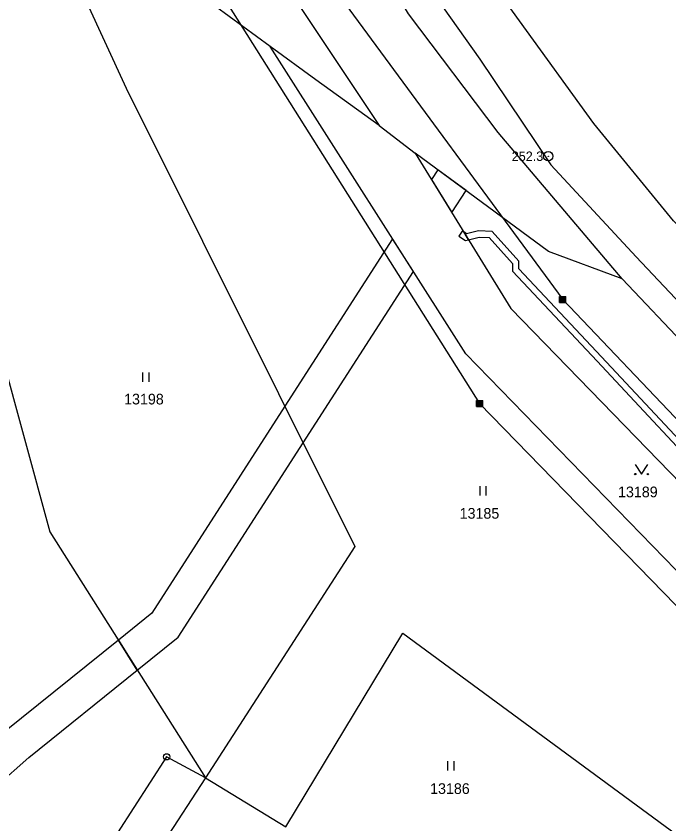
# Model space of a CAD drawing. Extents: x -821458 to -820266, y -1071458 to -1069826.
# Drawn here: x -820602.1 to -820498, y -1071105.6 to -1070976.8 of the extents above; entities that cross this region are included whole.
import ezdxf

# ---------------------------------------------------------------- set-up
doc = ezdxf.new("R2010")
doc.units = 0
for name, color, linetype in [('Vrstva 1', 7, 'Continuous'), ('Vrstva 13', 7, 'Continuous'), ('Vrstva 2', 7, 'Continuous'), ('Vrstva 3', 7, 'Continuous'), ('Vrstva 6', 7, 'Continuous'), ('Vrstva 8', 7, 'Continuous')]:
    doc.layers.add(name, color=color, linetype=linetype)

msp = doc.modelspace()

# ---------------------------------------------------------------- linework, layer by layer
at = {"layer": 'Vrstva 1'}
for p, q in [((-820561.6, -1070981.6), (-820570.28, -1070975.21)), ((-820544.2, -1070994.2), (-820538.47, -1070998.6)), ((-820517.2, -1071014.29), (-820538.47, -1070998.6)), ((-820505.46, -1071018.65), (-820517.2, -1071014.29)), ((-820488.98, -1071036.1), (-820505.46, -1071018.65)), ((-820571.9, -1071098.21), (-820578.53, -1071108.44)), ((-820571.9, -1071098.21), (-820559.1, -1071106.03))]:
    msp.add_line(p, q, dxfattribs=at)
for points in [[(-820505.46, -1071018.65), (-820525.24, -1070995.31), (-820539.52, -1070976.39), (-820562.83, -1070937.87), (-820572.14, -1070918.15), (-820580.6, -1070898.43)], [(-820575.41, -1070898.25), (-820570.53, -1070910.66), (-820562.59, -1070929.03), (-820552.69, -1070946.67), (-820539.84, -1070967.11), (-820528.16, -1070983.62), (-820516.84, -1071000.47), (-820503.22, -1071015.12), (-820488.13, -1071031.13), (-820440.56, -1071079.73), (-820404.7, -1071115.79), (-820365.81, -1071154.53), (-820359.33, -1071162.29), (-820347, -1071174.7)], [(-820482, -1071025.25), (-820497.26, -1071009.41), (-820509.99, -1070993.9), (-820521.81, -1070977.53), (-820533.63, -1070961.15), (-820544.37, -1070943.51), (-820553.9, -1070925.73), (-820562.49, -1070907.6), (-820567.72, -1070897.98)], [(-820623.8, -1070903.11), (-820584.54, -1070988.24), (-820548.09, -1071061.35), (-820571.9, -1071098.21)], [(-820580.4, -1070936.81), (-820577, -1070944.9), (-820544.2, -1070994.2)], [(-820435.54, -1071128.19), (-820530.4, -1071030.6), (-820561.6, -1070981.6)], [(-820544.2, -1070994.2), (-820554.3, -1070986.9), (-820561.6, -1070981.6)], [(-820538.47, -1070998.6), (-820523.2, -1071023.4), (-820427.22, -1071122.22)], [(-820612.61, -1071000.86), (-820596.7, -1071059), (-820571.9, -1071098.21)], [(-820559.1, -1071106.03), (-820540.45, -1071075.18), (-820452.17, -1071140.11)], [(-820571.9, -1071098.21), (-820578.09, -1071094.87), (-820585.93, -1071107.01), (-820584.55, -1071108.62), (-820592.5, -1071116.26), (-820603.93, -1071125.41), (-820635.05, -1071153.94)]]:
    msp.add_lwpolyline(points, dxfattribs=at)
at = {"layer": 'Vrstva 13'}
for points in [[(-820534.87, -1071001.25), (-820535.89, -1071002.8), (-820532.64, -1071008.07), (-820530.36, -1071004.58)], [(-820531.5, -1071011.87), (-820530.46, -1071012.55), (-820529.96, -1071012.43), (-820530.72, -1071011.18), (-820530.96, -1071011.03)], [(-820530.72, -1071011.18), (-820529.96, -1071012.43), (-820528.27, -1071012.02), (-820526.68, -1071012.07), (-820522.93, -1071016.2), (-820522.95, -1071017.41), (-820509.47, -1071031.79), (-820489.32, -1071053.34), (-820466.63, -1071077.97), (-820437.5, -1071107.65), (-820424.84, -1071120.52), (-820424.02, -1071119.92), (-820436.78, -1071106.95), (-820465.91, -1071077.29), (-820488.58, -1071052.66), (-820508.75, -1071031.11), (-820521.95, -1071017.03), (-820521.93, -1071015.82), (-820526.22, -1071011.09), (-820528.37, -1071011.02), (-820530.28, -1071011.47)], [(-820585.78, -1071076.26), (-820582.77, -1071081.03), (-820576.25, -1071075.78), (-820556.33, -1071044.81), (-820538.75, -1071017.48), (-820542.06, -1071012.28), (-820559.24, -1071038.98), (-820580.47, -1071071.98)], [(-820675.1, -1071148.28), (-820672.81, -1071153.44), (-820638.57, -1071131.55), (-820610.44, -1071104.1), (-820600.08, -1071094.97), (-820582.77, -1071081.03), (-820585.78, -1071076.26), (-820603.68, -1071090.69), (-820614.26, -1071100), (-820642.01, -1071127.07)]]:
    msp.add_lwpolyline(points, close=True, dxfattribs=at)
at = {"layer": 'Vrstva 3'}
for p, q in [((-820581.86, -1071035.09), (-820581.86, -1071033.59)), ((-820580.86, -1071035.09), (-820580.86, -1071033.59)), ((-820528.13, -1071053.2), (-820528.13, -1071051.7)), ((-820527.13, -1071053.2), (-820527.13, -1071051.7)), ((-820533.25, -1071097.06), (-820533.25, -1071095.56)), ((-820532.25, -1071097.06), (-820532.25, -1071095.56))]:
    msp.add_line(p, q, dxfattribs=at)
msp.add_lwpolyline([(-820503.38, -1071048.28), (-820502.38, -1071049.78), (-820501.38, -1071048.28)], dxfattribs=at)
for centre in [(-820503.38, -1071049.78), (-820501.38, -1071049.78)]:
    msp.add_circle(centre, 0.1, dxfattribs=at)
at = {"layer": 'Vrstva 6'}
for p, q in [((-820589.85, -1070920.06), (-820514.94, -1071021.94)), ((-820600.69, -1070923.5), (-820528.19, -1071038.53)), ((-820515.44, -1071021.44), (-820514.44, -1071021.44)), ((-820515.44, -1071022.44), (-820515.44, -1071021.44)), ((-820515.24, -1071022.44), (-820515.24, -1071021.44)), ((-820515.04, -1071022.44), (-820515.04, -1071021.44)), ((-820514.84, -1071022.44), (-820514.84, -1071021.44)), ((-820514.64, -1071022.44), (-820514.64, -1071021.44)), ((-820514.44, -1071022.44), (-820514.44, -1071021.44)), ((-820515.44, -1071021.64), (-820514.44, -1071021.64)), ((-820515.44, -1071021.84), (-820514.44, -1071021.84)), ((-820515.44, -1071022.04), (-820514.44, -1071022.04)), ((-820515.44, -1071022.24), (-820514.44, -1071022.24)), ((-820515.44, -1071022.44), (-820514.44, -1071022.44)), ((-820514.94, -1071021.94), (-820436.58, -1071104.39)), ((-820528.69, -1071038.03), (-820527.69, -1071038.03)), ((-820528.69, -1071039.03), (-820528.69, -1071038.03)), ((-820528.69, -1071038.23), (-820527.69, -1071038.23)), ((-820528.49, -1071039.03), (-820528.49, -1071038.03)), ((-820528.29, -1071039.03), (-820528.29, -1071038.03)), ((-820528.09, -1071039.03), (-820528.09, -1071038.03)), ((-820527.89, -1071039.03), (-820527.89, -1071038.03)), ((-820527.69, -1071039.03), (-820527.69, -1071038.03)), ((-820528.69, -1071038.43), (-820527.69, -1071038.43)), ((-820528.69, -1071038.63), (-820527.69, -1071038.63)), ((-820528.69, -1071038.83), (-820527.69, -1071038.83)), ((-820528.69, -1071039.03), (-820527.69, -1071039.03)), ((-820528.19, -1071038.53), (-820435.72, -1071133.7))]:
    msp.add_line(p, q, dxfattribs=at)
at = {"layer": 'Vrstva 8'}
for centre, radius in [((-820517.25, -1070999.1), 0.75), ((-820517.25, -1070999.1), 0.03), ((-820578.09, -1071094.87), 0.5), ((-820578.09, -1071094.87), 0.0303)]:
    msp.add_circle(centre, radius, dxfattribs=at)

# ---------------------------------------------------------------- texts
at = {"layer": 'Vrstva 2'}
for s, p in [('13198', (-820584.87, -1071038.68)), ('13189', (-820506.13, -1071053.48)), ('13185', (-820531.38, -1071056.9)), ('13186', (-820536.09, -1071100.79))]:
    msp.add_text(s, height=1.7, dxfattribs=at).set_placement(p)
at = {"layer": 'Vrstva 8'}
msp.add_text('252.3', height=1.5, dxfattribs=at).set_placement((-820523.07, -1070999.85))

doc.saveas('drawing.dxf')
